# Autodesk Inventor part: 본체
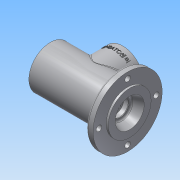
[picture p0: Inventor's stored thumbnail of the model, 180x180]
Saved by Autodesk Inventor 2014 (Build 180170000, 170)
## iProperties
Created: 2016-08
Part Number: 본체
Material: 알루미늄 6061
Document SubType Name: Modeling
Designer: 703
Density: 2.71 g/cm^3
Appearance: 알루미늄 - 평지
Author: 703
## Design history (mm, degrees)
sketch "스케치1"
  geometry: L1 (-57.5, 0)-(-57.5, 31); L2 (-57.5, 31)-(57.5, 31); L3 (57.5, 31)-(57.5, 21); L4 (57.5, 0)-(-57.5, 0); L5 (-48.5, 0)-(-48.5, 24); L6 (-48.5, 24)-(-45.5, 24); L7 (-45.5, 24)-(-45.5, 20); L8 (-45.5, 20)-(-36.5, 20); L9 (-36.5, 20)-(-36.5, 17.5); L10 (-36.5, 17.5)-(-33.25, 17.5); L11 (-33.25, 17.5)-(-33.25, 18.5); L12 (-33.25, 18.5)-(-31.5, 18.5); L13 (-31.5, 18.5)-(-31.5, 17.5); L14 (28.5, 17.2)-(28.5, 16.5); L15 (28.5, 16.5)-(30.5, 16.5); L16 (33.5, 13.5)-(33.5, 10); L17 (33.5, 10)-(36.2, 10); L18 (36.2, 10)-(36.2, 12.2); L19 (36.5, 12.5)-(42.8, 12.5); L20 (43.5, 12.904)-(43.5, 16); L21 (43.5, 16)-(57.5, 21); L22 (42.8, 12.5)-(43.5, 12.904); L23 (57.5, 21)-(57.5, 0); L24 (-20.5, 18.5)-(-20.5, 23); L25 (-17.5, 26)-(14.5, 26); L26 (17.5, 23)-(17.5, 18.5); L27 (-31.5, 17.5)-(-21.5, 17.5); L28 (18.5, 17.5)-(28.2, 17.5); L29 (-1.5, 26)-(-1.5, 0); L30 (-21.5, 17.5)-(-20.5, 18.5); L31 (17.5, 18.5)-(18.5, 17.5); A1 r 0.3 centre (28.2, 17.2) between (28.5, 17.2) and (28.2, 17.5); A2 r 0.3 centre (36.5, 12.2) between (36.5, 12.5) and (36.2, 12.2); A3 r 3 centre (-17.5, 23) between (-17.5, 26) and (-20.5, 23); A4 r 3 centre (14.5, 23) between (17.5, 23) and (14.5, 26); A5 r 3 centre (30.5, 13.5) between (33.5, 13.5) and (30.5, 16.5); 7 further points
  constraints: 62 end point, 18 parallel, 12 point on line, 11 tangent, 10 point on circle, 8 perpendicular, 5 centre point, 2 equal radius, 2 midpoint, 1 coincident, 1 vertical
  dimensions: "d1" = 62 diameter of L2 L4; "d2" = 48 diameter of L6 L4; "d3" = 40 diameter of L8 L4; "d4" = 35 diameter of L10 L4; "d5" = 37 diameter of L12 L4; "d7" = 33 diameter of L15 L4; "d8" = 20 diameter of L17 L4; "d9" = 25 diameter of L19 L4; "d10" = 32 diameter of L20.end L4; "d11" = 42 diameter of L3.end L4; "d12" = 14 distance between parallel lines of L3 L20; "d13" = 7.3 distance of point (36.2, 12.5) point (43.5, 12.5); "d14" = 2.7 distance of L16.end L17.end; "d15" = 60 distance between parallel lines of L14 L13; "d16" = 3 distance between parallel lines of L5 L7; "d17" = 9 distance between parallel lines of L9 L7; "d18" = 1.75 distance of L11.end L12.end; "d19" = 5 distance between parallel lines of L9 L13; "d20" = 21 distance between parallel lines of L1 L9; "d21" = 0.3 radius of A1; "d22" = 0.7 distance of L19.end point (43.5, 12.5); "d23" = 30 deg angle of L19 L22; "d41" = 38 distance between parallel lines of L26 L24; "d42" = 52 diameter of L25 L4; "d43" = 35 diameter of L27 L4; "d44" = 3 radius of A3; "d61" = 115 distance between parallel lines of L3 L1; "d62" = 56 distance between parallel lines of L1 L29; "d63" = 19 distance between parallel lines of L29 L24; "d106" = 3 radius of A5; "d107" = 1 distance of L27.end point (-20.5, 17.5); "d108" = 45 deg angle of L27 L30; "d109" = 1 distance of L26.end point (17.5, 17.5) (= d107); "d110" = 45 deg angle of L26 L31 (= d108)
revolve "회전1" sketch "스케치1" stored, may be unused: angle "d24" = 90 deg
fillet "모깎기1" dims "d25" = 3
hole "구멍1" diameter "d28" = 40.376; stored, may be unused: countersink angle "d32" = 90 deg, drill point angle "d34" = 0 deg; dims "d26" = 10, "d27" = 10, "d29" = 6, "d30" = 4, "d31" = 2, "d33" = 9
node "작업 평면1"
node "작업 평면2"
sketch "스케치6"
  geometry: C1 r 30 at (1.5, 0); 1 further point
  constraints: 1 centre point, 1 horizontal alignment
  dimensions: "d65" = 60 diameter of C1; "d66" = 1.5 distance of point (0, 0) C1.centre
extrude "돌출3" join sketch "스케치6" stored distance "d67" = 10; taper "d68" = 0 deg
sketch "스케치7"
  geometry: C1 r 30 at (0, 0) reference; C2 r 19 at (0, 0); 1 further point
  constraints: 1 centre point, 1 coincident
  dimensions: "d69" = 38 diameter of C2
extrude "돌출4" cut sketch "스케치7" distance "d70" = 50; taper "d71" = 0 deg
sketch "스케치8"
  geometry: C1 r 19 at (0, 0) reference; 2 further points
  constraints: 1 vertical alignment
  dimensions: "d72" = 24 distance of C1.centre point (0, 24)
hole "구멍3" sketch "스케치8" at (0, 24) diameter "d73" = 3.242; stored, may be unused: countersink angle "d77" = 90 deg, drill point angle "d79" = 118 deg; dims "d74" = 8, "d75" = 4, "d76" = 2, "d78" = 10
node "작업 평면3"
sketch "스케치9"
  geometry: L1 (-56, -80)-(-56, -18) reference; L2 (-30, 0)-(30, 0) reference; 2 further points
  constraints: 1 other
  dimensions: "d83" = 56 distance from line of L1 point (0, -10); "d85" = 10 distance from line of L2 point (0, -10)
feature "엠보싱1" sketch "스케치9" dims "d86" = 0.5, "d87" = 0
node "작업 평면4"
sketch "스케치10"
  geometry: C1 r 19.929 at (0, 0) reference; C2 r 31 at (0, 0) reference; C3 r 50 at (0, 0); C4 r 4 at (0, 41.5); C5 r 4 at (-41.5, 0); C6 r 4 at (41.5, 0); C7 r 4 at (0, -41.5); 1 further point
  constraints: 5 centre point, 2 horizontal alignment, 2 vertical alignment, 1 coincident
  dimensions: "d89" = 100 diameter of C3; "d90" = 8 diameter of C4; "d91" = 41.5 distance of point (0, 0) C4.centre; "d92" = 8 diameter of C5; "d93" = 8 diameter of C6; "d94" = 8 diameter of C7; "d95" = 41.5 distance of point (0, 0) C5.centre; "d96" = 41.5 distance of point (0, 0) C6.centre (= d95); "d97" = 41.5 distance of point (0, 0) C7.centre (= d96)
extrude "돌출5" join sketch "스케치10" distance "d98" = 10; taper "d99" = 0 deg
fillet "모깎기2" dims "d100" = 3
fillet "모깎기3" dims "d101" = 3
fillet "모깎기4" dims "d102" = 3
chamfer "모따기2" distance "d103" = 1; stored, may be unused: second distance "d104" = 2, angle "d105" = 45 deg
node "솔리드1"
pattern_circular "원형 패턴2" dims angle "d81" = 360 deg
node "절단 모서리 투영2"
other parameters: "d6" = 35, "d35" = 49, "d64" = 49, "d88" = -3
